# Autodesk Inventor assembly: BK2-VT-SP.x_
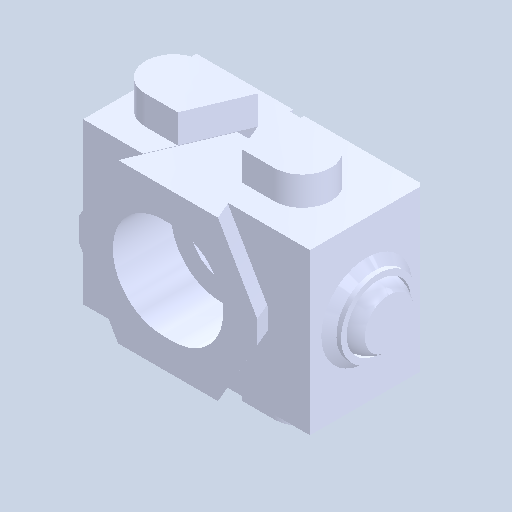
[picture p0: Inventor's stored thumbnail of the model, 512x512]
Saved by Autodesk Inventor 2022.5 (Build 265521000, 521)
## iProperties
Created: 2024-08
Part Number: BK2-VT-SP.x_
Document SubType Name: Assembly
Designer: ImaoCorp
Author: ImaoCorp
Sending System: SOLIDWORKS 2022-2022290
MC: AMD64
MC_MODEL: Intel64 Family 6 Model 60 Stepping 3, GenuineIntel
OS: Windows_NT
FRU: Parasolid Version 33.1, build 260,  4-25-2022
FORMAT: text
GUISE: transmit
KEY: FILEBK2-VT-SP.x_t
DATE: Fri Aug  2 11:42:37 2024
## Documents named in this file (4)
- X:\14_SW2022-Inv2022\07_2024-10新製品(WHS)\OKV_データ\b\bk2-vt-sp\BK2-VT-SP.x_.iam
- X:\14_SW2022-Inv2022\07_2024-10新製品(WHS)\OKV_データ\b\bk2-vt-sp\BK2-VT-SP_01.ipt
- X:\14_SW2022-Inv2022\07_2024-10新製品(WHS)\OKV_データ\b\bk2-vt-sp\BK2-VT-SP_02.ipt
- X:\14_SW2022-Inv2022\07_2024-10新製品(WHS)\OKV_データ\b\bk2-vt-sp\BK2-VT-SP_03.ipt
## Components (3 placed, 3 different names)
1. BK2-VT-SP_01
2. BK2-VT-SP_02
3. BK2-VT-SP_03
